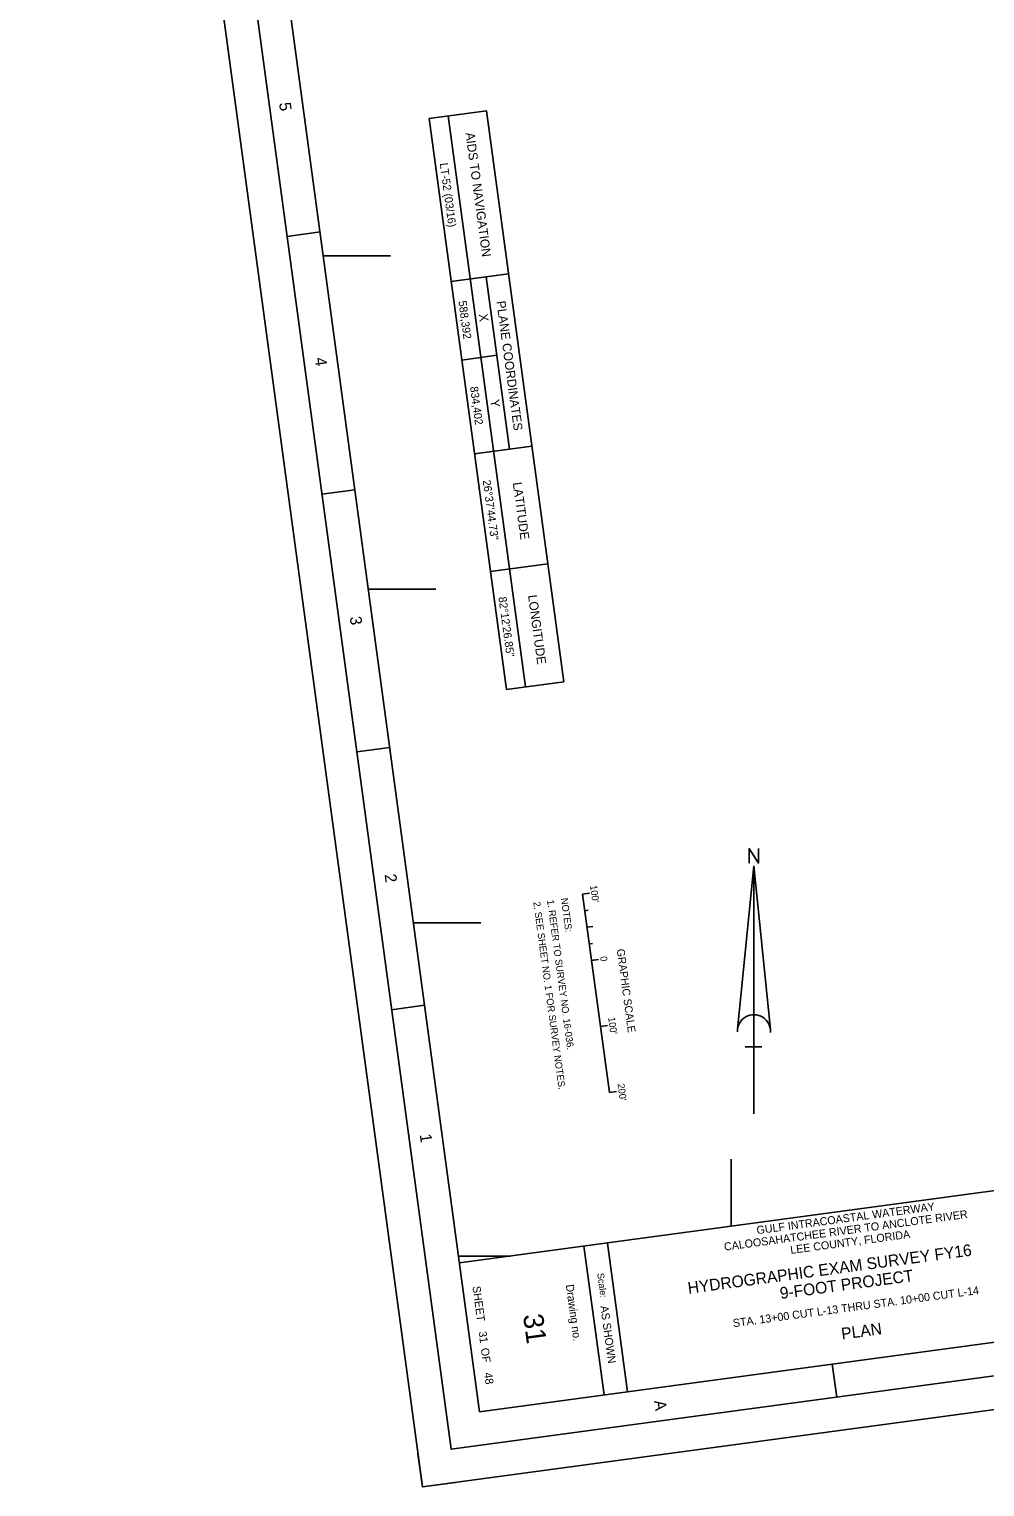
# Model space of a CAD drawing. Extents: x 586448 to 590407, y 831154 to 835970.
# Drawn here: x 586448 to 587880, y 831154 to 833340 of the extents above; entities that cross this region are included whole.
import ezdxf

# ---------------------------------------------------------------- set-up
doc = ezdxf.new("R2010")
doc.units = 0
for name, color, linetype in [('G-ANNO-NPLT', 7, 'Continuous'), ('G-ANNO-TEXT-DRWG', 7, 'Continuous'), ('G-ANNO-TEXT-PROJ', 7, 'Continuous'), ('G-ANNO-TEXT-TTLB', 7, 'Continuous'), ('G-ANNO-TTLB', 7, 'Continuous'), ('V-ANNO-NOTE', 7, 'Continuous'), ('V-ANNO-SCHD', 7, 'Continuous'), ('V-ANNO-SYMB', 7, 'Continuous'), ('V-TOPO-COOR-STAT', 7, 'Continuous')]:
    doc.layers.add(name, color=color, linetype=linetype)

msp = doc.modelspace()

# ---------------------------------------------------------------- linework, layer by layer
at = {"layer": 'G-ANNO-NPLT'}
msp.add_lwpolyline([(589817.4, 835970.1), (590406.9, 831609.7), (587037.5, 831154.3), (586448.1, 835514.6)], close=True, dxfattribs=at)
msp.add_lwpolyline([(587087.1, 831160.8), (587037.5, 831154.1), (587030.8, 831203.7)], dxfattribs=at)
at = {"layer": 'G-ANNO-TTLB'}
for p, q in [((586834.6, 833029), (586884.1, 833035.7)), ((586886.8, 832642.5), (586936.3, 832649.2)), ((586939, 832256), (586988.6, 832262.7)), ((590264.2, 831918.4), (587093.1, 831489.8)), ((586991.3, 831869.5), (587040.8, 831876.2)), ((587279.5, 831515), (587309.6, 831292)), ((587314.8, 831519.7), (587345, 831296.7)), ((587658.4, 831288.6), (587651.7, 831338.2))]:
    msp.add_line(p, q, dxfattribs=at)
for points in [[(586504.3, 835471.7), (587080.4, 831210.5), (590350.6, 831652.6), (589774.6, 835913.8)], [(590294.4, 831695.4), (589741.8, 835783.2), (586570.6, 835354.5), (587123.2, 831266.8)]]:
    msp.add_lwpolyline(points, close=True, dxfattribs=at)
at = {"layer": 'V-ANNO-NOTE'}
for p, q in [((587277.6, 832042.7), (587287.9, 832044.1)), ((587277.6, 832042.7), (587317.8, 831745.4)), ((587280.9, 832017.9), (587285.7, 832018.6)), ((587284.3, 831993.2), (587292.7, 831994.3)), ((587287.6, 831968.4), (587292.4, 831969)), ((587291, 831943.6), (587301.3, 831945)), ((587291, 831943.6), (587301.3, 831945)), ((587291, 831943.6), (587295.9, 831944.3)), ((587304.4, 831844.5), (587314.7, 831845.9)), ((587317.8, 831745.4), (587328.1, 831746.8))]:
    msp.add_line(p, q, dxfattribs=at)
at = {"layer": 'V-ANNO-SCHD'}
for p, q in [((587133.4, 833217.5), (587047.6, 833205.9)), ((587133.4, 833217.5), (587249.2, 832361.3)), ((587047.6, 833205.9), (587163.4, 832349.7)), ((587076.2, 833209.8), (587192, 832353.5)), ((587166.5, 832973.1), (587080.7, 832961.5)), ((587133.1, 832968.6), (587168, 832710.2)), ((587149, 832850.8), (587096.6, 832843.7)), ((587201.4, 832714.7), (587115.6, 832703.1)), ((587225.3, 832538), (587139.5, 832526.4)), ((587163.4, 832349.7), (587249.2, 832361.3))]:
    msp.add_line(p, q, dxfattribs=at)
at = {"layer": 'V-ANNO-SYMB'}
for p, q in [((587509.6, 831839.8), (587534.3, 832085.5)), ((587534.3, 831713.2), (587534.3, 832085.5)), ((587559, 831839.8), (587534.3, 832085.5)), ((587546.1, 831813.7), (587521.2, 831813.7))]:
    msp.add_line(p, q, dxfattribs=at)
msp.add_lwpolyline([(587527.4, 832089.5), (587527.4, 832111.2), (587541, 832089.5), (587541, 832111.2)], dxfattribs=at)
msp.add_arc((587534.3, 831837.3), 24.8, 355.2984, 182.0673, dxfattribs=at)
at = {"layer": 'V-TOPO-COOR-STAT'}
for p, q in [((586888.9, 833000), (586989.8, 833000)), ((586956.5, 832500), (587057.4, 832500)), ((587024.1, 832000), (587125, 832000)), ((587500, 831544.8), (587500, 831645.7)), ((587091.7, 831500), (587168.9, 831500))]:
    msp.add_line(p, q, dxfattribs=at)

# ---------------------------------------------------------------- texts
at = {"layer": 'G-ANNO-TEXT-DRWG'}
for s, height, rotation, p in [('STA. 13+00 CUT L-13 THRU STA. 10+00 CUT L-14', 12, 7.6988, (587503.6, 831393.5)), ('31', 30, 277.6988, (587188.2, 831411.6)), (' 31          48', 12, 277.6988, (587121, 831391.1)), ('PLAN', 17.5, 7.6988, (587666.4, 831374.9))]:
    msp.add_text(s, height=height, rotation=rotation, dxfattribs=at).set_placement(p)
at = {"layer": 'G-ANNO-TEXT-PROJ'}
for s, height, p in [('GULF INTRACOASTAL WATERWAY', 12, (587539.1, 831532.9)), ('CALOOSAHATCHEE RIVER TO ANCLOTE RIVER', 12, (587490.3, 831508.1)), ('LEE COUNTY, FLORIDA', 12, (587589.6, 831503.3)), ('HYDROGRAPHIC EXAM SURVEY FY16', 17.5, (587436.3, 831443.5)), ('9-FOOT PROJECT', 17.5, (587574.4, 831435.7))]:
    msp.add_text(s, height=height, rotation=7.6988, dxfattribs=at).set_placement(p)
at = {"layer": 'G-ANNO-TEXT-TTLB'}
for s, height, p in [('Scale:', 10, (587299.4, 831474.1)), ('SHEET         OF', 12, (587112.4, 831454.5)), ('Drawing no.', 12, (587252.3, 831456.9)), ('AS SHOWN', 12, (587304.1, 831425))]:
    msp.add_text(s, height=height, rotation=277.6988, dxfattribs=at).set_placement(p)
at = {"layer": 'G-ANNO-TTLB'}
for s, p in [('5', (586822.6, 833229)), ('4', (586876, 832846.5)), ('3', (586928.5, 832458.3)), ('2', (586980.7, 832072)), ('1', (587033.4, 831682.4)), ('A', (587384.6, 831282.9))]:
    msp.add_text(s, height=17.5, rotation=277.6988, dxfattribs=at).set_placement(p)
at = {"layer": 'V-ANNO-NOTE'}
for s, height, p in [('NOTES:', 10.42, (587244.9, 832036.5)), ("100'", 10.42, (587288.7, 832055.6)), ('2. SEE SHEET NO. 1 FOR SURVEY NOTES.', 10.416, (587203.6, 832030.9)), ('1. REFER TO SURVEY NO. 16-036.', 10.416, (587224.2, 832033.7)), ('0', 10.4, (587303.8, 831949.1)), ('GRAPHIC SCALE', 11.666, (587328.6, 831960)), ("100'", 10.42, (587315.8, 831857.8)), ("200'", 10.42, (587329.8, 831758.2))]:
    msp.add_text(s, height=height, rotation=277.6988, dxfattribs=at).set_placement(p)
at = {"layer": 'V-ANNO-SCHD'}
for s, height, p in [('AIDS TO NAVIGATION', 13.471, (587102, 833184.1)), ('PLANE COORDINATES', 13.471, (587148.3, 832931.6)), ('X', 13.5, (587121.8, 832912.4)), ('Y', 13.5, (587139.1, 832783.9)), ('LATITUDE', 13.47, (587172.9, 832659.7)), ('LONGITUDE', 13.47, (587195.7, 832490.8))]:
    msp.add_text(s, height=height, rotation=277.6988, dxfattribs=at).set_placement(p)
at = {"layer": 'V-ANNO-SYMB'}
for s, p in [('LT-52 (03/16)', (587063.5, 833138.6)), ('588,392', (587091.4, 832931.9)), ('834,402', (587108.8, 832803.3)), ('26%%D37\'44.73"', (587127.8, 832663.2)), ('82%%D12\'26.85"', (587151.4, 832488))]:
    msp.add_text(s, height=12, rotation=277.6988, dxfattribs=at).set_placement(p)

doc.saveas('drawing.dxf')
